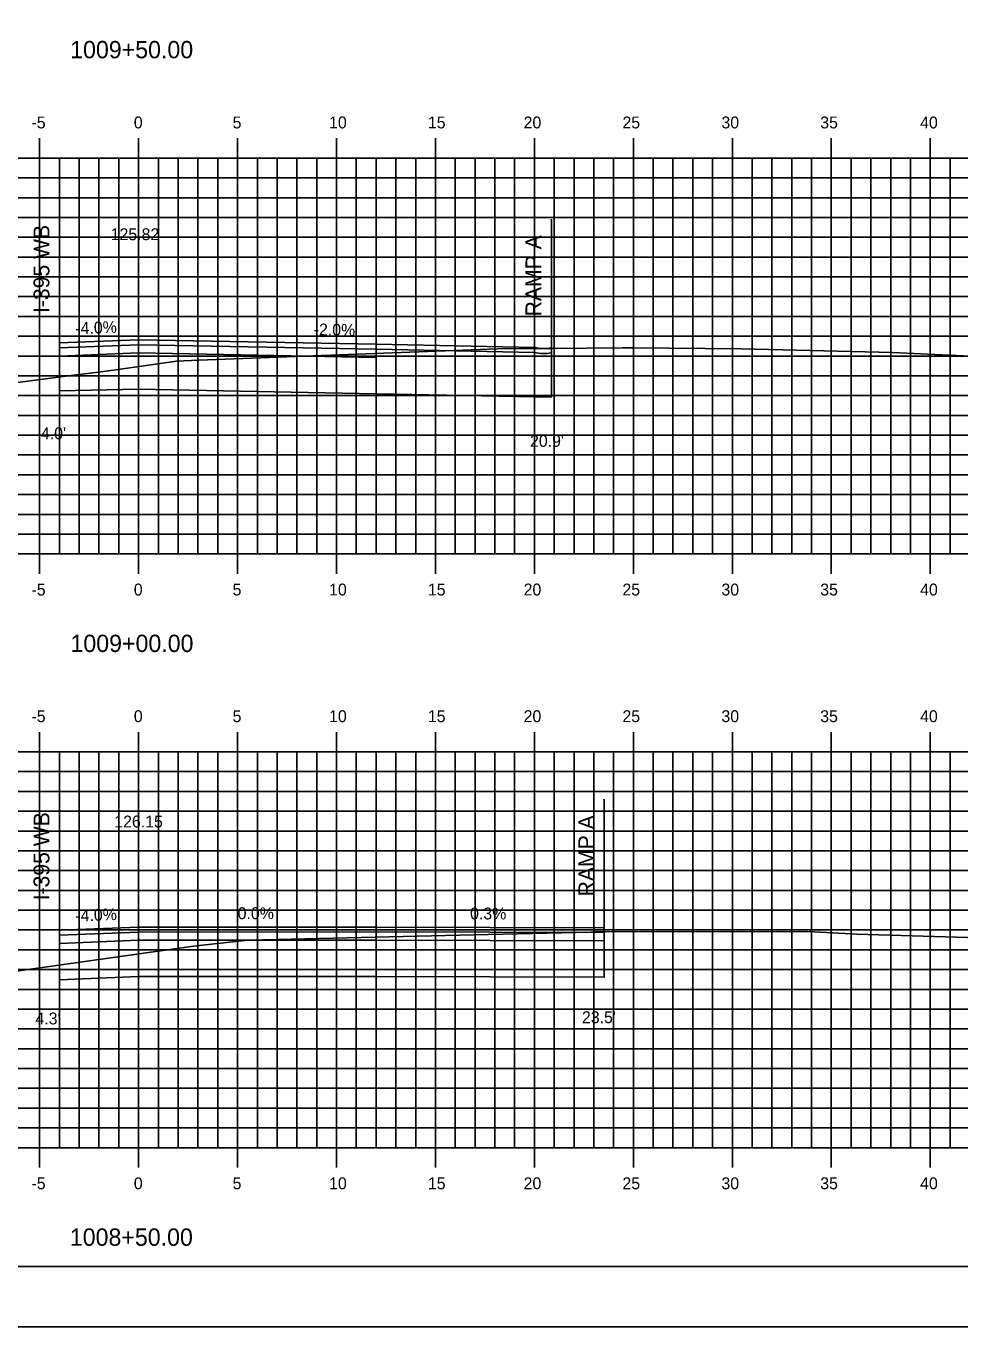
# Model space of a CAD drawing. Extents: x 851960 to 852132, y 365624 to 365734.
# Drawn here: x 852037.6 to 852084.8, y 365624 to 365689.7 of the extents above; entities that cross this region are included whole.
import ezdxf

# ---------------------------------------------------------------- set-up
doc = ezdxf.new("R2010")
doc.units = 0
for name, color, linetype in [('ANNOTATION', 7, 'Continuous'), ('BORDER', 7, 'Continuous'), ('D_Roadway_Centerline', 7, 'Continuous'), ('D_Roadway_Centerline_Text', 7, 'Continuous'), ('D_Roadway_Edge_Shoulder', 7, 'Continuous'), ('D_Roadway_Edge_TW', 7, 'Continuous'), ('D_Roadway_FinishedGrade', 7, 'Continuous'), ('D_Roadway_Pavement', 7, 'Continuous'), ('D_Roadway_SubGrade', 7, 'Continuous'), ('D_Text_Standard', 7, 'Continuous'), ('H_V ANNOTATION', 7, 'Continuous'), ('M_Roadway_Centerline', 7, 'Continuous'), ('MAJOR', 7, 'Continuous'), ('MINOR', 7, 'Continuous'), ('PLOT BOUNDARY', 7, 'Continuous'), ('S_Roadway_Centerline', 7, 'Continuous')]:
    doc.layers.add(name, color=color, linetype=linetype)

msp = doc.modelspace()

# ---------------------------------------------------------------- linework, layer by layer
at = {"layer": 'BORDER'}
msp.add_lwpolyline([(851968.279, 365627.027), (852128.279, 365627.027), (852128.279, 365732.027), (851968.279, 365732.027)], close=True, dxfattribs=at)
at = {"layer": 'D_Roadway_Centerline'}
for points in [[(852039.278, 365673.688), (852043.279, 365673.848), (852043.28, 365673.848), (852055.279, 365673.617), (852063.279, 365673.457)], [(852064.134, 365670.955), (852063.278, 365670.963)], [(852039.279, 365644.013), (852043.279, 365644.173), (852043.283, 365644.173), (852055.279, 365644.176), (852055.283, 365644.176), (852066.807, 365644.142)]]:
    msp.add_lwpolyline(points, dxfattribs=at)
msp.add_arc((852063.729, 365675.329), 1.925, 256.48074, 282.15272, dxfattribs=at)
at = {"layer": 'D_Roadway_Edge_Shoulder'}
for points in [[(852043.279, 365673.848), (852039.278, 365673.688), (852039.278, 365673.438), (852043.279, 365673.598)], [(852055.279, 365673.617), (852063.278, 365673.457), (852063.278, 365673.207), (852055.279, 365673.367)], [(852043.279, 365644.173), (852039.279, 365644.013), (852039.279, 365643.763), (852043.279, 365643.923)]]:
    msp.add_lwpolyline(points, close=True, dxfattribs=at)
at = {"layer": 'D_Roadway_Edge_TW'}
for points in [[(852043.279, 365673.848), (852055.279, 365673.617), (852055.279, 365673.367), (852043.279, 365673.598)], [(852043.279, 365644.173), (852055.279, 365644.176), (852055.279, 365643.926), (852043.279, 365643.923)], [(852055.279, 365644.176), (852066.807, 365644.142), (852066.807, 365643.892), (852055.279, 365643.926)]]:
    msp.add_lwpolyline(points, close=True, dxfattribs=at)
msp.add_lwpolyline([(852055.279, 365673.617), (852055.279, 365673.45)], dxfattribs=at)
at = {"layer": 'D_Roadway_FinishedGrade'}
for p, q in [((852039.278, 365673.688), (852039.278, 365673.438)), ((852043.279, 365673.848), (852043.279, 365673.598)), ((852055.279, 365673.617), (852055.279, 365673.367)), ((852063.278, 365673.457), (852063.278, 365673.207)), ((852064.134, 365673.447), (852064.134, 365673.197)), ((852039.279, 365644.013), (852039.279, 365643.763)), ((852043.279, 365644.173), (852043.279, 365643.923)), ((852055.279, 365644.176), (852055.279, 365643.926)), ((852066.807, 365644.142), (852066.807, 365643.892)), ((852066.807, 365644.142), (852066.807, 365643.892))]:
    msp.add_line(p, q, dxfattribs=at)
msp.add_arc((852063.743, 365675.197), 2.044, 256.87381, 281.0385, dxfattribs=at)
at = {"layer": 'D_Roadway_Pavement'}
for points in [[(852043.279, 365673.598), (852039.278, 365673.438), (852039.278, 365673.022), (852043.279, 365673.182)], [(852043.279, 365673.598), (852055.279, 365673.367), (852055.279, 365672.95), (852043.279, 365673.182)], [(852043.279, 365643.923), (852039.279, 365643.763), (852039.279, 365643.346), (852043.279, 365643.506)], [(852043.279, 365643.923), (852055.279, 365643.926), (852055.279, 365643.51), (852043.279, 365643.506)], [(852055.279, 365643.926), (852066.807, 365643.892), (852066.807, 365643.475), (852055.279, 365643.51)]]:
    msp.add_lwpolyline(points, close=True, dxfattribs=at)
msp.add_lwpolyline([(852055.279, 365673.45), (852055.279, 365672.95)], dxfattribs=at)
msp.add_lwpolyline([(852055.279, 365673.45), (852055.279, 365672.95)], dxfattribs=at)
at = {"layer": 'D_Roadway_SubGrade'}
for p, q in [((852039.278, 365680.185), (852039.278, 365671.268)), ((852064.134, 365679.944), (852064.134, 365670.955)), ((852039.279, 365650.51), (852039.279, 365641.513)), ((852066.807, 365650.639), (852066.807, 365641.642))]:
    msp.add_line(p, q, dxfattribs=at)
for points in [[(852043.279, 365673.182), (852039.278, 365673.022), (852039.278, 365673.522), (852039.278, 365673.688), (852039.278, 365671.268), (852043.279, 365671.348)], [(852055.279, 365672.95), (852055.279, 365673.367), (852063.278, 365673.207), (852063.278, 365673.457), (852063.278, 365670.963), (852055.279, 365671.117)], [(852043.279, 365673.182), (852055.279, 365672.95), (852055.279, 365671.117), (852043.279, 365671.348)], [(852043.279, 365643.506), (852039.279, 365643.346), (852039.279, 365643.846), (852039.279, 365644.013), (852039.279, 365641.513), (852043.279, 365641.673)], [(852043.279, 365643.506), (852055.279, 365643.51), (852055.279, 365641.676), (852043.279, 365641.673)], [(852055.279, 365643.51), (852066.807, 365643.475), (852066.807, 365641.642), (852055.279, 365641.676)]]:
    msp.add_lwpolyline(points, close=True, dxfattribs=at)
for points in [[(852055.279, 365672.95), (852055.279, 365671.117)], [(852064.134, 365673.191), (852064.134, 365670.955)]]:
    msp.add_lwpolyline(points, dxfattribs=at)
at = {"layer": 'MAJOR'}
for p, q in [((852038.279, 365684.029), (852038.279, 365683.027)), ((852043.279, 365684.029), (852043.279, 365683.027)), ((852048.279, 365684.029), (852048.279, 365683.027)), ((852053.279, 365684.029), (852053.279, 365683.027)), ((852058.279, 365684.029), (852058.279, 365683.027)), ((852063.279, 365684.029), (852063.279, 365683.027)), ((852068.279, 365684.029), (852068.279, 365683.027)), ((852073.279, 365684.029), (852073.279, 365683.027)), ((852078.279, 365684.029), (852078.279, 365683.027)), ((852083.279, 365684.029), (852083.279, 365683.027)), ((851973.279, 365683.027), (852113.279, 365683.027)), ((851973.279, 365683.027), (852113.279, 365683.027)), ((852038.279, 365663.027), (852038.279, 365683.027)), ((852043.279, 365663.027), (852043.279, 365683.027)), ((852048.279, 365663.027), (852048.279, 365683.027)), ((852053.279, 365663.027), (852053.279, 365683.027)), ((852058.279, 365663.027), (852058.279, 365683.027)), ((852063.279, 365663.027), (852063.279, 365683.027)), ((852068.279, 365663.027), (852068.279, 365683.027)), ((852073.279, 365663.027), (852073.279, 365683.027)), ((852078.279, 365663.027), (852078.279, 365683.027)), ((852083.279, 365663.027), (852083.279, 365683.027)), ((851973.279, 365678.027), (852113.279, 365678.027)), ((851973.279, 365673.027), (852113.279, 365673.027)), ((851973.279, 365668.027), (852113.279, 365668.027)), ((851973.279, 365663.027), (852113.279, 365663.027)), ((851973.279, 365663.027), (852113.279, 365663.027)), ((852038.279, 365662.025), (852038.279, 365663.027)), ((852043.279, 365662.025), (852043.279, 365663.027)), ((852048.279, 365662.025), (852048.279, 365663.027)), ((852053.279, 365662.025), (852053.279, 365663.027)), ((852058.279, 365662.025), (852058.279, 365663.027)), ((852063.279, 365662.025), (852063.279, 365663.027)), ((852068.279, 365662.025), (852068.279, 365663.027)), ((852073.279, 365662.025), (852073.279, 365663.027)), ((852078.279, 365662.025), (852078.279, 365663.027)), ((852083.279, 365662.025), (852083.279, 365663.027)), ((852038.279, 365654.029), (852038.279, 365653.027)), ((852043.279, 365654.029), (852043.279, 365653.027)), ((852048.279, 365654.029), (852048.279, 365653.027)), ((852053.279, 365654.029), (852053.279, 365653.027)), ((852058.279, 365654.029), (852058.279, 365653.027)), ((852063.279, 365654.029), (852063.279, 365653.027)), ((852068.279, 365654.029), (852068.279, 365653.027)), ((852073.279, 365654.029), (852073.279, 365653.027)), ((852078.279, 365654.029), (852078.279, 365653.027)), ((852083.279, 365654.029), (852083.279, 365653.027)), ((851973.279, 365653.027), (852113.279, 365653.027)), ((851973.279, 365653.027), (852113.279, 365653.027)), ((852038.279, 365633.027), (852038.279, 365653.027)), ((852043.279, 365633.027), (852043.279, 365653.027)), ((852048.279, 365633.027), (852048.279, 365653.027)), ((852053.279, 365633.027), (852053.279, 365653.027)), ((852058.279, 365633.027), (852058.279, 365653.027)), ((852063.279, 365633.027), (852063.279, 365653.027)), ((852068.279, 365633.027), (852068.279, 365653.027)), ((852073.279, 365633.027), (852073.279, 365653.027)), ((852078.279, 365633.027), (852078.279, 365653.027)), ((852083.279, 365633.027), (852083.279, 365653.027)), ((851973.279, 365648.027), (852113.279, 365648.027)), ((851973.279, 365643.027), (852113.279, 365643.027)), ((851973.279, 365638.027), (852113.279, 365638.027)), ((851973.279, 365633.027), (852113.279, 365633.027)), ((851973.279, 365633.027), (852113.279, 365633.027)), ((852038.279, 365632.025), (852038.279, 365633.027)), ((852043.279, 365632.025), (852043.279, 365633.027)), ((852048.279, 365632.025), (852048.279, 365633.027)), ((852053.279, 365632.025), (852053.279, 365633.027)), ((852058.279, 365632.025), (852058.279, 365633.027)), ((852063.279, 365632.025), (852063.279, 365633.027)), ((852068.279, 365632.025), (852068.279, 365633.027)), ((852073.279, 365632.025), (852073.279, 365633.027)), ((852078.279, 365632.025), (852078.279, 365633.027)), ((852083.279, 365632.025), (852083.279, 365633.027))]:
    msp.add_line(p, q, dxfattribs=at)
at = {"layer": 'MINOR'}
for p, q in [((852039.279, 365663.027), (852039.279, 365683.027)), ((852040.279, 365663.027), (852040.279, 365683.027)), ((852041.279, 365663.027), (852041.279, 365683.027)), ((852042.279, 365663.027), (852042.279, 365683.027)), ((852044.279, 365663.027), (852044.279, 365683.027)), ((852045.279, 365663.027), (852045.279, 365683.027)), ((852046.279, 365663.027), (852046.279, 365683.027)), ((852047.279, 365663.027), (852047.279, 365683.027)), ((852049.279, 365663.027), (852049.279, 365683.027)), ((852050.279, 365663.027), (852050.279, 365683.027)), ((852051.279, 365663.027), (852051.279, 365683.027)), ((852052.279, 365663.027), (852052.279, 365683.027)), ((852054.279, 365663.027), (852054.279, 365683.027)), ((852055.279, 365663.027), (852055.279, 365683.027)), ((852056.279, 365663.027), (852056.279, 365683.027)), ((852057.279, 365663.027), (852057.279, 365683.027)), ((852059.279, 365663.027), (852059.279, 365683.027)), ((852060.279, 365663.027), (852060.279, 365683.027)), ((852061.279, 365663.027), (852061.279, 365683.027)), ((852062.279, 365663.027), (852062.279, 365683.027)), ((852064.279, 365663.027), (852064.279, 365683.027)), ((852065.279, 365663.027), (852065.279, 365683.027)), ((852066.279, 365663.027), (852066.279, 365683.027)), ((852067.279, 365663.027), (852067.279, 365683.027)), ((852069.279, 365663.027), (852069.279, 365683.027)), ((852070.279, 365663.027), (852070.279, 365683.027)), ((852071.279, 365663.027), (852071.279, 365683.027)), ((852072.279, 365663.027), (852072.279, 365683.027)), ((852074.279, 365663.027), (852074.279, 365683.027)), ((852075.279, 365663.027), (852075.279, 365683.027)), ((852076.279, 365663.027), (852076.279, 365683.027)), ((852077.279, 365663.027), (852077.279, 365683.027)), ((852079.279, 365663.027), (852079.279, 365683.027)), ((852080.279, 365663.027), (852080.279, 365683.027)), ((852081.279, 365663.027), (852081.279, 365683.027)), ((852082.279, 365663.027), (852082.279, 365683.027)), ((852084.279, 365663.027), (852084.279, 365683.027)), ((851973.279, 365682.027), (852113.279, 365682.027)), ((851973.279, 365681.027), (852113.279, 365681.027)), ((851973.279, 365680.027), (852113.279, 365680.027)), ((851973.279, 365679.027), (852113.279, 365679.027)), ((851973.279, 365677.027), (852113.279, 365677.027)), ((851973.279, 365676.027), (852113.279, 365676.027)), ((851973.279, 365675.027), (852113.279, 365675.027)), ((851973.279, 365674.027), (852113.279, 365674.027)), ((851973.279, 365672.027), (852113.279, 365672.027)), ((851973.279, 365671.027), (852113.279, 365671.027)), ((851973.279, 365670.027), (852113.279, 365670.027)), ((851973.279, 365669.027), (852113.279, 365669.027)), ((851973.279, 365667.027), (852113.279, 365667.027)), ((851973.279, 365666.027), (852113.279, 365666.027)), ((851973.279, 365665.027), (852113.279, 365665.027)), ((851973.279, 365664.027), (852113.279, 365664.027)), ((852039.279, 365633.027), (852039.279, 365653.027)), ((852040.279, 365633.027), (852040.279, 365653.027)), ((852041.279, 365633.027), (852041.279, 365653.027)), ((852042.279, 365633.027), (852042.279, 365653.027)), ((852044.279, 365633.027), (852044.279, 365653.027)), ((852045.279, 365633.027), (852045.279, 365653.027)), ((852046.279, 365633.027), (852046.279, 365653.027)), ((852047.279, 365633.027), (852047.279, 365653.027)), ((852049.279, 365633.027), (852049.279, 365653.027)), ((852050.279, 365633.027), (852050.279, 365653.027)), ((852051.279, 365633.027), (852051.279, 365653.027)), ((852052.279, 365633.027), (852052.279, 365653.027)), ((852054.279, 365633.027), (852054.279, 365653.027)), ((852055.279, 365633.027), (852055.279, 365653.027)), ((852056.279, 365633.027), (852056.279, 365653.027)), ((852057.279, 365633.027), (852057.279, 365653.027)), ((852059.279, 365633.027), (852059.279, 365653.027)), ((852060.279, 365633.027), (852060.279, 365653.027)), ((852061.279, 365633.027), (852061.279, 365653.027)), ((852062.279, 365633.027), (852062.279, 365653.027)), ((852064.279, 365633.027), (852064.279, 365653.027)), ((852065.279, 365633.027), (852065.279, 365653.027)), ((852066.279, 365633.027), (852066.279, 365653.027)), ((852067.279, 365633.027), (852067.279, 365653.027)), ((852069.279, 365633.027), (852069.279, 365653.027)), ((852070.279, 365633.027), (852070.279, 365653.027)), ((852071.279, 365633.027), (852071.279, 365653.027)), ((852072.279, 365633.027), (852072.279, 365653.027)), ((852074.279, 365633.027), (852074.279, 365653.027)), ((852075.279, 365633.027), (852075.279, 365653.027)), ((852076.279, 365633.027), (852076.279, 365653.027)), ((852077.279, 365633.027), (852077.279, 365653.027)), ((852079.279, 365633.027), (852079.279, 365653.027)), ((852080.279, 365633.027), (852080.279, 365653.027)), ((852081.279, 365633.027), (852081.279, 365653.027)), ((852082.279, 365633.027), (852082.279, 365653.027)), ((852084.279, 365633.027), (852084.279, 365653.027)), ((851973.279, 365652.027), (852113.279, 365652.027)), ((851973.279, 365651.027), (852113.279, 365651.027)), ((851973.279, 365650.027), (852113.279, 365650.027)), ((851973.279, 365649.027), (852113.279, 365649.027)), ((851973.279, 365647.027), (852113.279, 365647.027)), ((851973.279, 365646.027), (852113.279, 365646.027)), ((851973.279, 365645.027), (852113.279, 365645.027)), ((851973.279, 365644.027), (852113.279, 365644.027)), ((851973.279, 365642.027), (852113.279, 365642.027)), ((851973.279, 365641.027), (852113.279, 365641.027)), ((851973.279, 365640.027), (852113.279, 365640.027)), ((851973.279, 365639.027), (852113.279, 365639.027)), ((851973.279, 365637.027), (852113.279, 365637.027)), ((851973.279, 365636.027), (852113.279, 365636.027)), ((851973.279, 365635.027), (852113.279, 365635.027)), ((851973.279, 365634.027), (852113.279, 365634.027))]:
    msp.add_line(p, q, dxfattribs=at)
at = {"layer": 'PLOT BOUNDARY'}
msp.add_lwpolyline([(851960.186, 365623.968), (852130.186, 365623.968), (852130.186, 365733.968), (851960.186, 365733.968)], close=True, dxfattribs=at)
at = {"layer": 'S_Roadway_Centerline'}
for points in [[(852022.178, 365669.718), (852039.605, 365672.002), (852041.639, 365672.256), (852042.244, 365672.337), (852045.2, 365672.758), (852046.319, 365672.812), (852061.426, 365673.397), (852064.162, 365673.412), (852067.719, 365673.448), (852068.232, 365673.445), (852073.739, 365673.386), (852081.376, 365673.205), (852088.518, 365672.867), (852088.754, 365672.888), (852099.895, 365671.68), (852101.06, 365671.555), (852102.582, 365671.375), (852105.106, 365670.856), (852113.279, 365669.238)], [(852032.313, 365641.267), (852046.057, 365643.213), (852048.797, 365643.52), (852050.265, 365643.55), (852060.208, 365643.782), (852066.129, 365643.91), (852066.28, 365643.93), (852074.212, 365643.956), (852077.434, 365643.941), (852079.573, 365643.815), (852086.849, 365643.591), (852088.814, 365643.281), (852090.788, 365643.024), (852102.051, 365641.698), (852109, 365640.503), (852113.279, 365639.529)]]:
    msp.add_lwpolyline(points, dxfattribs=at)

# ---------------------------------------------------------------- texts
at = {"layer": 'ANNOTATION'}
for s, height, rotation, p in [('I-395 WB', 0.8, 90, (852038.772, 365675.195)), ('RAMP A', 0.8, 90, (852063.627, 365675.028)), ('-4.0%', 0.6, 2.29042, (852040.095, 365674.121)), ('-2.0%', 0.6, 358.87999, (852052.122, 365674.075)), ('I-395 WB', 0.8, 90, (852038.772, 365645.52)), ('RAMP A', 0.8, 90, (852066.3, 365645.723)), ('0.0%', 0.6, 0.01431, (852048.285, 365644.574)), ('0.3%', 0.6, 359.83099, (852060.026, 365644.562)), ('-4.0%', 0.6, 2.29039, (852040.096, 365644.446))]:
    msp.add_text(s, height=height, rotation=rotation, dxfattribs=at).set_placement(p)
at = {"layer": 'D_Roadway_Centerline'}
for s, p in [('C', (852043.273, 365673.848)), ('L', (852043.279, 365673.84)), ('C', (852043.274, 365644.173)), ('L', (852043.279, 365644.165))]:
    msp.add_text(s, height=0.0146, dxfattribs=at).set_placement(p)
at = {"layer": 'D_Roadway_Centerline_Text'}
for s, p in [('125.82', (852041.869, 365678.88)), ('126.15', (852042.051, 365649.205))]:
    msp.add_text(s, height=0.6, dxfattribs=at).set_placement(p)
at = {"layer": 'D_Text_Standard'}
for s, p in [("4.0'", (852038.345, 365668.821)), ("20.9'", (852063.056, 365668.438)), ("23.5'", (852065.681, 365639.318)), ("4.3'", (852038.068, 365639.255))]:
    msp.add_text(s, height=0.6, dxfattribs=at).set_placement(p)
at = {"layer": 'H_V ANNOTATION'}
for s, height, p in [('1009+50.00', 0.875, (852039.822, 365688.07)), ('-5', 0.6, (852037.869, 365684.527)), ('0', 0.6, (852043.038, 365684.527)), ('5', 0.6, (852048.03, 365684.527)), ('10', 0.6, (852052.904, 365684.527)), ('15', 0.6, (852057.896, 365684.527)), ('20', 0.6, (852062.733, 365684.527)), ('25', 0.6, (852067.725, 365684.527)), ('30', 0.6, (852072.727, 365684.527)), ('35', 0.6, (852077.719, 365684.527)), ('40', 0.6, (852082.765, 365684.527)), ('-5', 0.6, (852037.869, 365660.927)), ('0', 0.6, (852043.038, 365660.927)), ('5', 0.6, (852048.03, 365660.927)), ('10', 0.6, (852052.904, 365660.927)), ('15', 0.6, (852057.896, 365660.927)), ('20', 0.6, (852062.733, 365660.927)), ('25', 0.6, (852067.725, 365660.927)), ('30', 0.6, (852072.727, 365660.927)), ('35', 0.6, (852077.719, 365660.927)), ('40', 0.6, (852082.765, 365660.927)), ('1009+00.00', 0.875, (852039.838, 365658.07)), ('-5', 0.6, (852037.869, 365654.527)), ('0', 0.6, (852043.038, 365654.527)), ('5', 0.6, (852048.03, 365654.527)), ('10', 0.6, (852052.904, 365654.527)), ('15', 0.6, (852057.896, 365654.527)), ('20', 0.6, (852062.733, 365654.527)), ('25', 0.6, (852067.725, 365654.527)), ('30', 0.6, (852072.727, 365654.527)), ('35', 0.6, (852077.719, 365654.527)), ('40', 0.6, (852082.765, 365654.527)), ('-5', 0.6, (852037.869, 365630.927)), ('0', 0.6, (852043.038, 365630.927)), ('5', 0.6, (852048.03, 365630.927)), ('10', 0.6, (852052.904, 365630.927)), ('15', 0.6, (852057.896, 365630.927)), ('20', 0.6, (852062.733, 365630.927)), ('25', 0.6, (852067.725, 365630.927)), ('30', 0.6, (852072.727, 365630.927)), ('35', 0.6, (852077.719, 365630.927)), ('40', 0.6, (852082.765, 365630.927)), ('1008+50.00', 0.875, (852039.806, 365628.07))]:
    msp.add_text(s, height=height, dxfattribs=at).set_placement(p)
at = {"layer": 'M_Roadway_Centerline'}
for s, p in [('C', (852067.714, 365673.448)), ('L', (852067.719, 365673.44)), ('C', (852066.275, 365643.93)), ('L', (852066.28, 365643.923))]:
    msp.add_text(s, height=0.0146, dxfattribs=at).set_placement(p)

doc.saveas('drawing.dxf')
